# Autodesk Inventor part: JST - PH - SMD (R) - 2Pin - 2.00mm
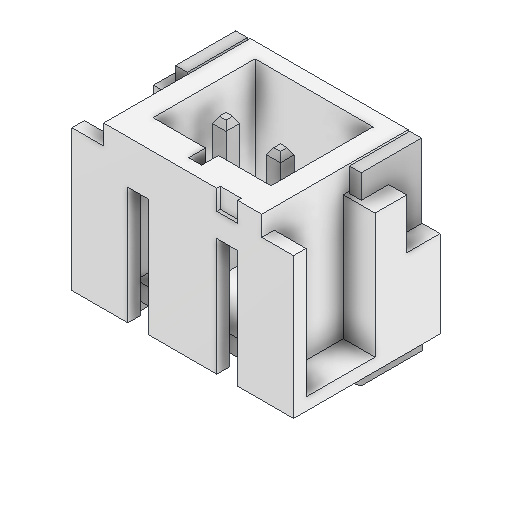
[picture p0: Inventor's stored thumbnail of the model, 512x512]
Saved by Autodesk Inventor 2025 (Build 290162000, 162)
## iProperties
Created: 2025-05
Part Number: JST - PH - SMD (R) - 2Pin - 2.00mm
Material: Generico
Document SubType Name: Modeling
Designer: R5800u
Density: 1 g/cm^3
Appearance: Default
Author: R5800u
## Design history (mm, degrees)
feature "Base1"
node "Solido1"
